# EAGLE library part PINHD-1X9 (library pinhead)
PIN HEADER
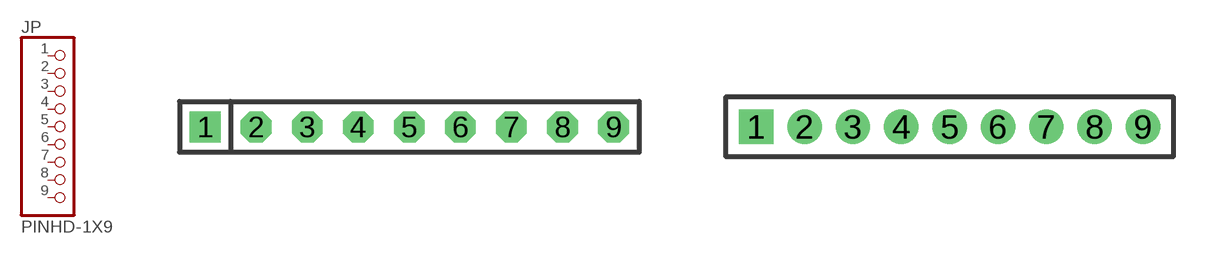
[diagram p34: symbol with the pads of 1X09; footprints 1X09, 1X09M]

Designator prefix JP

## PINHD-1X9  [1X09]
1  1  pas
2  2  pas
3  3  pas
4  4  pas
5  5  pas
6  6  pas
7  7  pas
8  8  pas
9  9  pas

## PINHD-1X9M  [1X09M]
Pads as for 1X09

## Footprint 1X09 (pad centres in mm)
PIN HEADER - 0.1"
drill 1.016 square: 1 -10.16,0
drill 1.016 octagon: 2 -7.62,0; 3 -5.08,0; 4 -2.54,0; 5 0,0; 6 2.54,0; 7 5.08,0; 8 7.62,0; 9 10.16,0

## Footprint 1X09M (pad centres in mm)
PIN HEADER - 2MM"
drill 0.914 square: 1 -8,0
drill 0.914 round: 2 -6,0; 3 -4,0; 4 -2,0; 5 0,0; 6 2,0; 7 4,0; 8 6,0; 9 8,0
